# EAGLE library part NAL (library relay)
RELAY
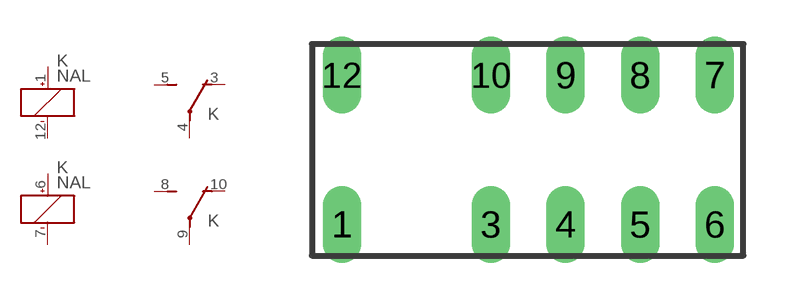
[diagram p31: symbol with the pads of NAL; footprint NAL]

Designator prefix K; gates 1=K+- 2=K+- 3=U 4=U

## NAL (OC_FARNELL: unknown; OC_NEWARK: unknown)  [NAL]
1  1:+  pas
3  3:O  pas
4  3:P  pas
5  3:S  pas
6  2:+  pas
7  2:-  pas
8  4:S  pas
9  4:P  pas
10  4:O  pas
12  1:-  pas

## Footprint NAL (pad centres in mm)
RELAY dummy long
drill 0.8 long: 1 -6.35,-2.54; 3 -1.27,-2.54; 4 1.27,-2.54; 5 3.81,-2.54; 6 6.35,-2.54; 7 6.35,2.54; 8 3.81,2.54; 9 1.27,2.54; 10 -1.27,2.54; 12 -6.35,2.54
